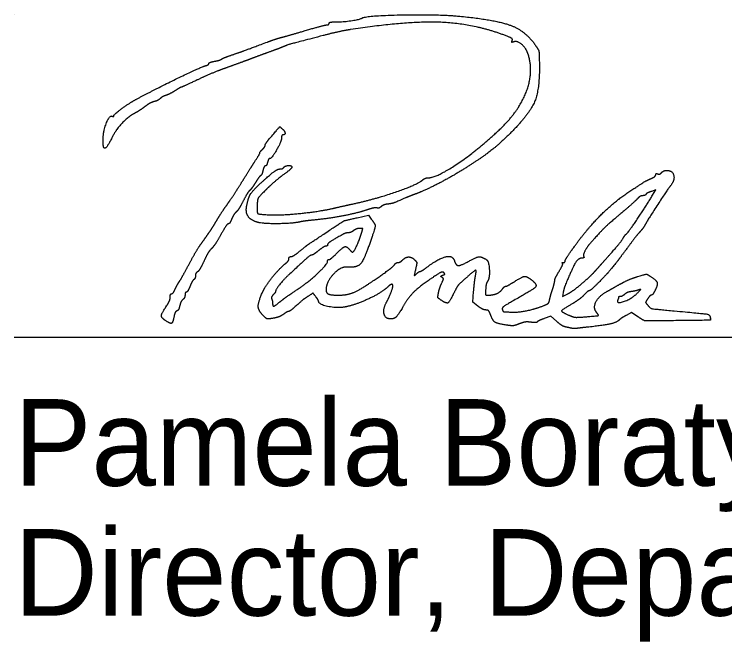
# Model space of a CAD drawing. Extents: x -8.2 to 38.5, y -0.1 to 21.9.
# Drawn here: x 24.597 to 25.745, y 6.87 to 7.884 of the extents above; entities that cross this region are included whole.
import ezdxf

# ---------------------------------------------------------------- set-up
doc = ezdxf.new("R2010")
doc.units = 0
doc.layers.add('GM_X_Adjacent_County', color=7, linetype='Continuous')
doc.layers.add('GM_X_Township', color=7, linetype='Continuous')

msp = doc.modelspace()

# ---------------------------------------------------------------- linework, layer by layer
at = {"layer": 'GM_X_Adjacent_County'}
for points in [[(25.6284, 7.5917), (25.6338, 7.6006), (25.6265, 7.598)], [(25.1511, 7.5555), (25.1691, 7.5595), (25.1738, 7.5534)], [(25.346, 7.4127), (25.3377, 7.419), (25.3392, 7.4361)], [(25.484, 7.4347), (25.483, 7.4282), (25.4917, 7.4326)], [(25.6049, 7.3953), (25.5942, 7.4022), (25.5858, 7.3976)], [(25.473, 7.3883), (25.4638, 7.3966), (25.4533, 7.3925)]]:
    msp.add_lwpolyline(points, dxfattribs=at)
for points in [[(25.1585, 7.8781), (25.1653, 7.8823), (25.2823, 7.8845), (25.3167, 7.8812)], [(25.3167, 7.8812), (25.376, 7.8753), (25.4235, 7.857), (25.4393, 7.834)], [(25.1018, 7.8671), (25.1038, 7.8671), (25.1055, 7.8683), (25.1055, 7.8696)], [(25.1055, 7.8696), (25.1055, 7.871), (25.1096, 7.872), (25.1145, 7.8719)], [(25.1145, 7.8719), (25.1241, 7.8716), (25.1551, 7.8759), (25.1585, 7.8781)], [(25.3892, 7.8504), (25.3386, 7.8694), (25.2307, 7.8734), (25.1403, 7.8596)], [(25.0299, 7.8473), (25.0352, 7.8487), (25.0527, 7.8537), (25.0688, 7.8585)], [(25.0688, 7.8585), (25.0849, 7.8632), (25.0997, 7.8671), (25.1018, 7.8671)], [(25.1403, 7.8596), (25.1311, 7.8582), (25.1111, 7.8539), (25.0959, 7.8499)], [(25.0059, 7.8395), (25.0138, 7.8424), (25.0246, 7.846), (25.0299, 7.8473)], [(25.0959, 7.8499), (25.0449, 7.8367), (25.0406, 7.8355), (25.0299, 7.8311)], [(25.4015, 7.8418), (25.4025, 7.8443), (25.399, 7.8467), (25.3892, 7.8504)], [(24.9495, 7.8189), (24.9642, 7.824), (24.9707, 7.8264), (25.0059, 7.8395)], [(25.4039, 7.8397), (25.4013, 7.8387), (25.4006, 7.8394), (25.4015, 7.8418)], [(25.4273, 7.8198), (25.4241, 7.8296), (25.4096, 7.8419), (25.4039, 7.8397)], [(25.4393, 7.834), (25.4443, 7.8267), (25.4452, 7.8224), (25.4455, 7.8045)], [(25.0071, 7.8227), (24.9972, 7.8191), (24.9821, 7.8135), (24.9735, 7.8102)], [(25.0299, 7.8311), (25.0273, 7.8301), (25.017, 7.8263), (25.0071, 7.8227)], [(24.9201, 7.8083), (24.9251, 7.8092), (24.9302, 7.8108), (24.9315, 7.8117)], [(24.9315, 7.8117), (24.9328, 7.8127), (24.9409, 7.816), (24.9495, 7.8189)], [(25.3818, 7.6986), (25.4128, 7.728), (25.4366, 7.7916), (25.4273, 7.8198)], [(24.7935, 7.7467), (24.8237, 7.763), (24.8973, 7.7986), (24.9057, 7.8011)], [(24.9057, 7.8011), (24.9087, 7.8019), (24.9111, 7.8035), (24.9111, 7.8046)], [(24.9111, 7.8046), (24.9111, 7.8057), (24.9152, 7.8074), (24.9201, 7.8083)], [(24.9735, 7.8102), (24.9649, 7.807), (24.9487, 7.8011), (24.9375, 7.7971)], [(25.4455, 7.8045), (25.4462, 7.7638), (25.4301, 7.7241), (25.4007, 7.6942)], [(24.9375, 7.7971), (24.9263, 7.7931), (24.9059, 7.7846), (24.8923, 7.7781)], [(24.8923, 7.7781), (24.8786, 7.7716), (24.867, 7.7663), (24.8664, 7.7663)], [(24.8664, 7.7663), (24.8659, 7.7663), (24.8614, 7.7638), (24.8565, 7.7607)], [(24.8416, 7.7532), (24.8384, 7.7521), (24.8343, 7.7498), (24.8325, 7.748)], [(24.8565, 7.7607), (24.8515, 7.7576), (24.8449, 7.7542), (24.8416, 7.7532)], [(24.7575, 7.7201), (24.7575, 7.7223), (24.7829, 7.741), (24.7935, 7.7467)], [(24.8227, 7.7432), (24.8192, 7.7423), (24.8125, 7.7387), (24.8079, 7.7351)], [(24.8325, 7.748), (24.8306, 7.7462), (24.8263, 7.744), (24.8227, 7.7432)], [(24.8079, 7.7351), (24.8033, 7.7315), (24.7961, 7.7269), (24.792, 7.7248)], [(24.7403, 7.6822), (24.7404, 7.6954), (24.7511, 7.722), (24.7552, 7.7195)], [(24.7552, 7.7195), (24.7565, 7.7187), (24.7575, 7.719), (24.7575, 7.7201)], [(24.792, 7.7248), (24.7816, 7.7194), (24.7617, 7.6986), (24.7555, 7.6865)], [(25.0077, 7.6812), (25.0262, 7.7033), (25.0256, 7.7027), (25.0296, 7.6994)], [(25.0296, 7.6994), (25.0339, 7.6958), (25.0349, 7.6895), (25.0311, 7.6895)], [(25.2651, 7.6199), (25.2792, 7.6199), (25.3473, 7.6658), (25.3818, 7.6986)], [(24.7555, 7.6865), (24.7489, 7.6736), (24.7436, 7.6667), (24.7417, 7.6685)], [(25.0287, 7.6844), (25.0287, 7.6789), (25.0128, 7.6511), (25.0096, 7.6511)], [(25.0311, 7.6895), (25.0298, 7.6895), (25.0287, 7.6872), (25.0287, 7.6844)], [(25.4007, 7.6942), (25.3821, 7.6753), (25.3497, 7.6504), (25.3192, 7.6315)], [(24.7417, 7.6685), (24.7409, 7.6693), (24.7403, 7.6755), (24.7403, 7.6822)], [(24.9975, 7.6655), (25.0001, 7.6682), (25.0023, 7.6713), (25.0023, 7.6725)], [(25.0023, 7.6725), (25.0023, 7.6737), (25.0047, 7.6776), (25.0077, 7.6812)], [(24.9938, 7.6607), (24.9932, 7.6607), (24.9949, 7.6629), (24.9975, 7.6655)], [(24.9848, 7.6451), (24.9903, 7.6537), (24.9943, 7.6607), (24.9938, 7.6607)], [(25.0096, 7.6511), (25.0085, 7.6511), (25.007, 7.6484), (25.0061, 7.6451)], [(24.9627, 7.6101), (24.9693, 7.6207), (24.9792, 7.6365), (24.9848, 7.6451)], [(25.0025, 7.6391), (25.0013, 7.6391), (24.9996, 7.6359), (24.9987, 7.632)], [(25.0061, 7.6451), (25.0053, 7.6418), (25.0036, 7.6391), (25.0025, 7.6391)], [(25.0323, 7.6367), (25.0341, 7.6396), (25.0455, 7.64), (25.0455, 7.6371)], [(24.9939, 7.6102), (25.0096, 7.6248), (25.0224, 7.6343), (25.0263, 7.6343)], [(24.9987, 7.632), (24.9978, 7.628), (24.9961, 7.6241), (24.9948, 7.6234)], [(25.0263, 7.6343), (25.0288, 7.6343), (25.0315, 7.6354), (25.0323, 7.6367)], [(25.0455, 7.6371), (25.0455, 7.636), (25.0388, 7.6301), (25.0305, 7.624)], [(25.3192, 7.6315), (25.3001, 7.6197), (25.2588, 7.5987), (25.2447, 7.5936)], [(25.6335, 7.6249), (25.6335, 7.6264), (25.635, 7.6271), (25.6369, 7.6263)], [(25.6369, 7.6263), (25.6388, 7.6256), (25.6416, 7.6266), (25.6432, 7.6285)], [(25.6432, 7.6285), (25.6448, 7.6304), (25.6485, 7.6319), (25.6514, 7.6319)], [(25.6514, 7.6319), (25.6609, 7.6319), (25.6646, 7.6159), (25.6572, 7.6069)], [(24.9948, 7.6234), (24.9936, 7.6226), (24.9897, 7.6174), (24.9864, 7.6119)], [(25.0305, 7.624), (25.0223, 7.6179), (25.0098, 7.607), (25.0027, 7.5998)], [(25.1451, 7.578), (25.182, 7.5862), (25.2483, 7.6091), (25.2569, 7.6166)], [(25.2569, 7.6166), (25.259, 7.6184), (25.2627, 7.6199), (25.2651, 7.6199)], [(25.5967, 7.6015), (25.6157, 7.6138), (25.6175, 7.6149), (25.6257, 7.6186)], [(25.6257, 7.6186), (25.63, 7.6205), (25.6335, 7.6233), (25.6335, 7.6249)], [(24.941, 7.5771), (24.9463, 7.5846), (24.9561, 7.5994), (24.9627, 7.6101)], [(24.9726, 7.5755), (24.9753, 7.5886), (24.9815, 7.5986), (24.9939, 7.6102)], [(24.9864, 7.6119), (24.983, 7.6064), (24.9788, 7.6008), (24.9772, 7.5995)], [(25.6572, 7.6069), (25.6531, 7.6019), (25.6202, 7.5514), (25.6171, 7.5453)], [(24.9772, 7.5995), (24.9755, 7.5982), (24.9709, 7.5905), (24.9668, 7.5826)], [(25.0027, 7.5998), (24.992, 7.5889), (24.9898, 7.5852), (24.9893, 7.577)], [(25.2447, 7.5936), (25.2401, 7.5919), (25.2331, 7.5891), (25.2291, 7.5874)], [(25.5021, 7.509), (25.5244, 7.5398), (25.5694, 7.5839), (25.5967, 7.6015)], [(25.6178, 7.5933), (25.617, 7.5921), (25.6146, 7.5911), (25.6124, 7.5911)], [(25.6265, 7.598), (25.6224, 7.5966), (25.6185, 7.5945), (25.6178, 7.5933)], [(24.9668, 7.5826), (24.9628, 7.5746), (24.9577, 7.5666), (24.9556, 7.5648)], [(25.2291, 7.5874), (25.212, 7.58), (25.2071, 7.5783), (25.2005, 7.5775)], [(25.6036, 7.5857), (25.6009, 7.5828), (25.5884, 7.5717), (25.5759, 7.5612)], [(25.5856, 7.5287), (25.5884, 7.5307), (25.6167, 7.5722), (25.6284, 7.5917)], [(25.6124, 7.5911), (25.6103, 7.5911), (25.6063, 7.5887), (25.6036, 7.5857)], [(24.9242, 7.5515), (24.9281, 7.5581), (24.9356, 7.5697), (24.941, 7.5771)], [(24.9879, 7.5487), (24.9775, 7.5526), (24.9704, 7.565), (24.9726, 7.5755)], [(24.9893, 7.577), (24.9885, 7.5635), (24.9925, 7.5607), (25.0131, 7.5601)], [(25.0131, 7.5601), (25.0324, 7.5596), (25.0902, 7.5657), (25.1115, 7.5705)], [(25.1115, 7.5705), (25.1194, 7.5723), (25.1345, 7.5757), (25.1451, 7.578)], [(25.1829, 7.5713), (25.1812, 7.5719), (25.1731, 7.5702), (25.1649, 7.5675)], [(25.1897, 7.5734), (25.1876, 7.5716), (25.1846, 7.5707), (25.1829, 7.5713)], [(25.2005, 7.5775), (25.1966, 7.5771), (25.1918, 7.5752), (25.1897, 7.5734)], [(24.9556, 7.5648), (24.9534, 7.563), (24.9501, 7.5579), (24.9483, 7.5535)], [(25.1649, 7.5675), (25.1484, 7.5622), (25.1033, 7.5538), (25.0796, 7.5515)], [(25.5759, 7.5612), (25.5563, 7.5446), (25.5446, 7.5332), (25.5279, 7.5144)], [(24.9112, 7.5309), (24.9145, 7.5356), (24.9204, 7.5449), (24.9242, 7.5515)], [(24.9483, 7.5535), (24.9465, 7.5491), (24.9439, 7.5455), (24.9426, 7.5455)], [(25.0592, 7.5488), (25.0454, 7.5458), (24.9959, 7.5457), (24.9879, 7.5487)], [(25.0796, 7.5515), (25.0712, 7.5507), (25.062, 7.5495), (25.0592, 7.5488)], [(25.0971, 7.5291), (25.1288, 7.5501), (25.1302, 7.5508), (25.1511, 7.5555)], [(25.1738, 7.5534), (25.1804, 7.5446), (25.1802, 7.5397), (25.1725, 7.5172)], [(24.9426, 7.5455), (24.9413, 7.5455), (24.9359, 7.5376), (24.9306, 7.528)], [(25.1453, 7.5347), (25.1427, 7.5327), (25.1388, 7.5311), (25.1365, 7.5311)], [(25.1551, 7.5383), (25.1523, 7.5382), (25.1478, 7.5366), (25.1453, 7.5347)], [(25.1584, 7.5317), (25.1601, 7.5375), (25.1597, 7.5383), (25.1551, 7.5383)], [(25.6171, 7.5453), (25.6153, 7.5418), (25.6114, 7.5364), (25.6084, 7.5331)], [(24.8976, 7.5117), (24.9018, 7.5175), (24.9078, 7.5261), (24.9112, 7.5309)], [(24.9306, 7.528), (24.9252, 7.5183), (24.9185, 7.5083), (24.9157, 7.5058)], [(25.0579, 7.5012), (25.0716, 7.5122), (25.0696, 7.5108), (25.0971, 7.5291)], [(25.1268, 7.528), (25.1124, 7.5201), (25.1031, 7.5137), (25.1031, 7.5117)], [(25.1365, 7.5311), (25.1343, 7.5311), (25.1299, 7.5297), (25.1268, 7.528)], [(25.1438, 7.4999), (25.1456, 7.4999), (25.1553, 7.5211), (25.1584, 7.5317)], [(25.5504, 7.4858), (25.5658, 7.5029), (25.5793, 7.5193), (25.5817, 7.5236)], [(25.5817, 7.5236), (25.5829, 7.5258), (25.5847, 7.5281), (25.5856, 7.5287)], [(25.6084, 7.5331), (25.6054, 7.5299), (25.5965, 7.5186), (25.5886, 7.5079)], [(24.8788, 7.4795), (24.885, 7.4914), (24.8935, 7.5059), (24.8976, 7.5117)], [(25.1031, 7.5117), (25.1031, 7.5105), (25.1019, 7.5095), (25.1005, 7.5095)], [(25.1725, 7.5172), (25.1623, 7.4873), (25.1503, 7.4742), (25.1343, 7.4756)], [(25.5279, 7.5144), (25.5221, 7.5077), (25.5158, 7.4949), (25.5172, 7.4925)], [(24.9157, 7.5058), (24.9129, 7.5032), (24.9073, 7.4941), (24.9034, 7.4855)], [(25.0441, 7.4927), (25.0459, 7.4927), (25.0521, 7.4965), (25.0579, 7.5012)], [(25.0887, 7.5023), (25.0837, 7.4984), (25.0787, 7.4951), (25.0776, 7.4951)], [(25.1005, 7.5095), (25.099, 7.5095), (25.0937, 7.5063), (25.0887, 7.5023)], [(25.1175, 7.4975), (25.1276, 7.5077), (25.1342, 7.5095), (25.1391, 7.5035)], [(25.1391, 7.5035), (25.1408, 7.5016), (25.1428, 7.4999), (25.1438, 7.4999)], [(25.4871, 7.4857), (25.4871, 7.4871), (25.4939, 7.4976), (25.5021, 7.509)], [(25.5886, 7.5079), (25.5807, 7.4973), (25.5731, 7.4871), (25.5716, 7.4852)], [(25.0353, 7.4815), (25.0383, 7.4839), (25.0407, 7.4874), (25.0407, 7.4893)], [(25.0407, 7.4893), (25.0407, 7.4912), (25.0422, 7.4927), (25.0441, 7.4927)], [(25.0776, 7.4951), (25.0757, 7.4951), (25.0672, 7.4879), (25.0419, 7.4646)], [(25.1055, 7.4879), (25.1068, 7.4879), (25.1122, 7.4923), (25.1175, 7.4975)], [(25.2243, 7.487), (25.2292, 7.492), (25.2392, 7.4921), (25.2441, 7.4871)], [(25.2623, 7.4745), (25.2825, 7.4896), (25.3052, 7.4952), (25.3082, 7.4858)], [(25.332, 7.4854), (25.344, 7.492), (25.3512, 7.4928), (25.3594, 7.4882)], [(25.515, 7.4903), (25.5086, 7.4903), (25.4991, 7.4752), (25.4871, 7.4459)], [(25.5172, 7.4925), (25.518, 7.4913), (25.517, 7.4903), (25.515, 7.4903)], [(24.8633, 7.4519), (24.8655, 7.4552), (24.8725, 7.4677), (24.8788, 7.4795)], [(24.9034, 7.4855), (24.8995, 7.477), (24.8947, 7.4691), (24.8929, 7.468)], [(24.9972, 7.4333), (25.0017, 7.4437), (25.0249, 7.4732), (25.0353, 7.4815)], [(25.057, 7.4414), (25.0726, 7.4518), (25.1031, 7.4805), (25.1031, 7.4848)], [(25.1031, 7.4848), (25.1031, 7.4865), (25.1042, 7.4879), (25.1055, 7.4879)], [(25.1691, 7.4483), (25.1877, 7.4606), (25.2101, 7.4773), (25.2118, 7.4801)], [(25.2118, 7.4801), (25.2129, 7.4818), (25.2152, 7.4831), (25.2171, 7.4831)], [(25.2171, 7.4831), (25.2189, 7.4831), (25.2221, 7.4849), (25.2243, 7.487)], [(25.2441, 7.4871), (25.2473, 7.484), (25.2475, 7.4815), (25.2454, 7.4723)], [(25.3082, 7.4858), (25.3106, 7.4782), (25.3187, 7.4781), (25.332, 7.4854)], [(25.3594, 7.4882), (25.3638, 7.4857), (25.3655, 7.4577), (25.3616, 7.4525)], [(25.4773, 7.4688), (25.4812, 7.4751), (25.4837, 7.4809), (25.4829, 7.4817)], [(25.4829, 7.4817), (25.4822, 7.4825), (25.4828, 7.4831), (25.4843, 7.4831)], [(25.4843, 7.4831), (25.4858, 7.4831), (25.4871, 7.4843), (25.4871, 7.4857)], [(25.5348, 7.4683), (25.5379, 7.4718), (25.545, 7.4797), (25.5504, 7.4858)], [(25.5716, 7.4852), (25.5583, 7.4688), (25.5538, 7.4637), (25.5419, 7.4515)], [(24.8929, 7.468), (24.891, 7.467), (24.8895, 7.4641), (24.8895, 7.4616)], [(25.1343, 7.4756), (25.1239, 7.4765), (25.1007, 7.4511), (25.1007, 7.4388)], [(25.2454, 7.4723), (25.2431, 7.4621), (25.2432, 7.4616), (25.247, 7.465)], [(25.247, 7.465), (25.2493, 7.4671), (25.2519, 7.4687), (25.2529, 7.4687)], [(25.2529, 7.4687), (25.2538, 7.4687), (25.2581, 7.4713), (25.2623, 7.4745)], [(25.291, 7.4667), (25.2891, 7.4685), (25.2832, 7.4657), (25.2708, 7.4572)], [(25.2893, 7.4625), (25.2923, 7.4636), (25.2928, 7.4648), (25.291, 7.4667)], [(25.3421, 7.4609), (25.344, 7.4704), (25.3414, 7.4708), (25.3321, 7.4626)], [(25.4703, 7.4541), (25.4703, 7.4559), (25.4735, 7.4625), (25.4773, 7.4688)], [(25.5147, 7.4495), (25.5226, 7.4563), (25.5317, 7.4648), (25.5348, 7.4683)], [(24.887, 7.4555), (24.8856, 7.4546), (24.8828, 7.4497), (24.8807, 7.4445)], [(24.8895, 7.4616), (24.8895, 7.4591), (24.8884, 7.4563), (24.887, 7.4555)], [(25.0419, 7.4646), (25.0328, 7.4562), (25.0191, 7.4392), (25.0191, 7.4362)], [(25.2708, 7.4572), (25.251, 7.4438), (25.2338, 7.4267), (25.2255, 7.4123)], [(25.2881, 7.459), (25.2859, 7.4604), (25.2862, 7.4613), (25.2893, 7.4625)], [(25.2874, 7.4492), (25.2903, 7.4554), (25.2904, 7.4576), (25.2881, 7.459)], [(25.3321, 7.4626), (25.3161, 7.4486), (25.3124, 7.4441), (25.3069, 7.4328)], [(25.3392, 7.4361), (25.34, 7.4455), (25.3413, 7.4566), (25.3421, 7.4609)], [(25.4329, 7.4549), (25.4426, 7.4473), (25.4358, 7.4394), (25.4042, 7.4217)], [(25.4047, 7.4519), (25.4177, 7.4602), (25.4252, 7.461), (25.4329, 7.4549)], [(25.5747, 7.4475), (25.5826, 7.452), (25.5958, 7.4577), (25.604, 7.4602)], [(25.604, 7.4602), (25.6181, 7.4644), (25.6192, 7.4644), (25.6251, 7.4606)], [(25.6251, 7.4606), (25.6347, 7.4543), (25.6371, 7.4469), (25.6325, 7.4379)], [(24.8564, 7.4393), (24.858, 7.443), (24.8611, 7.4486), (24.8633, 7.4519)], [(24.8807, 7.4445), (24.8787, 7.4394), (24.876, 7.4351), (24.8748, 7.4351)], [(25.1207, 7.4303), (25.1337, 7.4303), (25.1528, 7.4374), (25.1691, 7.4483)], [(25.2011, 7.4441), (25.1915, 7.435), (25.1528, 7.4162), (25.1343, 7.4117)], [(25.1981, 7.4183), (25.2023, 7.426), (25.2087, 7.4423), (25.2087, 7.445)], [(25.2087, 7.445), (25.2087, 7.4481), (25.2047, 7.4476), (25.2011, 7.4441)], [(25.2823, 7.4335), (25.2831, 7.4377), (25.2854, 7.4447), (25.2874, 7.4492)], [(25.3616, 7.4525), (25.3603, 7.4509), (25.359, 7.4452), (25.3587, 7.4399)], [(25.3856, 7.4399), (25.3874, 7.4425), (25.39, 7.4447), (25.3912, 7.4447)], [(25.3912, 7.4447), (25.3924, 7.4447), (25.3985, 7.448), (25.4047, 7.4519)], [(25.4668, 7.4399), (25.4687, 7.4459), (25.4703, 7.4522), (25.4703, 7.4541)], [(25.4871, 7.4459), (25.486, 7.4433), (25.4846, 7.4382), (25.484, 7.4347)], [(25.4917, 7.4326), (25.4964, 7.4351), (25.5068, 7.4427), (25.5147, 7.4495)], [(25.5419, 7.4515), (25.5344, 7.4438), (25.5274, 7.4375), (25.5263, 7.4375)], [(25.5551, 7.4365), (25.558, 7.438), (25.5668, 7.443), (25.5747, 7.4475)], [(24.8487, 7.4271), (24.8487, 7.4302), (24.8498, 7.4327), (24.8512, 7.4327)], [(24.8512, 7.4327), (24.8525, 7.4327), (24.8549, 7.4357), (24.8564, 7.4393)], [(24.8748, 7.4351), (24.8737, 7.4351), (24.8727, 7.4331), (24.8727, 7.4306)], [(24.9989, 7.3975), (24.9913, 7.4052), (24.9907, 7.418), (24.9972, 7.4333)], [(25.0191, 7.4362), (25.0191, 7.4354), (25.0174, 7.4331), (25.0154, 7.4311)], [(25.0255, 7.419), (25.033, 7.4251), (25.0383, 7.4288), (25.057, 7.4414)], [(25.0841, 7.4278), (25.0796, 7.4336), (25.0796, 7.4336), (25.0728, 7.4292)], [(25.1007, 7.4388), (25.1007, 7.4337), (25.1085, 7.4303), (25.1207, 7.4303)], [(25.2869, 7.422), (25.2819, 7.4253), (25.2812, 7.4273), (25.2823, 7.4335)], [(25.3069, 7.4328), (25.3002, 7.4191), (25.2954, 7.4165), (25.2869, 7.422)], [(25.3587, 7.4399), (25.3581, 7.4323), (25.3588, 7.4303), (25.362, 7.4303)], [(25.362, 7.4303), (25.3703, 7.4303), (25.3823, 7.4352), (25.3856, 7.4399)], [(25.462, 7.4229), (25.4627, 7.4263), (25.4649, 7.434), (25.4668, 7.4399)], [(25.5263, 7.4375), (25.5252, 7.4375), (25.5213, 7.4344), (25.5177, 7.4306)], [(25.5381, 7.4021), (25.532, 7.4095), (25.5418, 7.4292), (25.5551, 7.4365)], [(25.5721, 7.4222), (25.5696, 7.4157), (25.595, 7.4246), (25.6035, 7.4333)], [(25.5831, 7.4315), (25.5809, 7.4296), (25.5779, 7.4279), (25.5763, 7.4279)], [(25.5941, 7.4361), (25.5902, 7.4355), (25.5853, 7.4335), (25.5831, 7.4315)], [(25.6059, 7.4388), (25.6033, 7.4378), (25.598, 7.4366), (25.5941, 7.4361)], [(25.6035, 7.4333), (25.609, 7.4388), (25.6096, 7.4402), (25.6059, 7.4388)], [(25.6325, 7.4379), (25.6303, 7.4337), (25.6277, 7.4303), (25.6265, 7.4303)], [(24.8429, 7.4128), (24.8461, 7.4176), (24.8487, 7.424), (24.8487, 7.4271)], [(24.8693, 7.4233), (24.8674, 7.4217), (24.8651, 7.4172), (24.8642, 7.4132)], [(24.8727, 7.4306), (24.8727, 7.4282), (24.8712, 7.4248), (24.8693, 7.4233)], [(25.0154, 7.4311), (25.0133, 7.429), (25.0122, 7.4257), (25.013, 7.4238)], [(25.013, 7.4238), (25.0137, 7.4219), (25.0143, 7.4188), (25.0143, 7.4169)], [(25.0728, 7.4292), (25.0646, 7.4238), (25.062, 7.4218), (25.0508, 7.4117)], [(25.0887, 7.4204), (25.0886, 7.4212), (25.0866, 7.4246), (25.0841, 7.4278)], [(25.1343, 7.4117), (25.1214, 7.4086), (25.0888, 7.4148), (25.0887, 7.4204)], [(25.4042, 7.4217), (25.3909, 7.4142), (25.3847, 7.4094), (25.3856, 7.4072)], [(25.4493, 7.4122), (25.4581, 7.4156), (25.4611, 7.4181), (25.462, 7.4229)], [(25.5177, 7.4306), (25.5141, 7.4268), (25.506, 7.4206), (25.4997, 7.417)], [(25.5735, 7.4269), (25.5735, 7.4264), (25.5729, 7.4242), (25.5721, 7.4222)], [(25.5763, 7.4279), (25.5748, 7.4279), (25.5735, 7.4275), (25.5735, 7.4269)], [(25.6207, 7.4245), (25.6171, 7.4192), (25.6172, 7.4183), (25.621, 7.4136)], [(25.6265, 7.4303), (25.6254, 7.4303), (25.6227, 7.4277), (25.6207, 7.4245)], [(24.8412, 7.3891), (24.8342, 7.394), (24.8347, 7.4007), (24.8429, 7.4128)], [(24.8642, 7.4132), (24.8634, 7.4092), (24.8612, 7.4055), (24.8595, 7.4048)], [(25.0143, 7.4169), (25.0143, 7.4121), (25.0177, 7.4127), (25.0255, 7.419)], [(25.0508, 7.4117), (25.046, 7.4074), (25.0412, 7.4039), (25.0401, 7.4039)], [(25.2049, 7.3919), (25.1965, 7.3919), (25.1924, 7.4077), (25.1981, 7.4183)], [(25.2255, 7.4123), (25.2173, 7.3982), (25.211, 7.3919), (25.2049, 7.3919)], [(25.3591, 7.4063), (25.3565, 7.4063), (25.3506, 7.4092), (25.346, 7.4127)], [(25.3995, 7.4029), (25.41, 7.4023), (25.4362, 7.4072), (25.4493, 7.4122)], [(25.4997, 7.417), (25.4818, 7.4066), (25.4808, 7.4033), (25.4937, 7.3977)], [(25.621, 7.4136), (25.6247, 7.4091), (25.6296, 7.408), (25.6635, 7.4049)], [(24.8595, 7.4048), (24.8578, 7.4041), (24.8557, 7.4), (24.8549, 7.3956)], [(25.0151, 7.3929), (25.0064, 7.3916), (25.0042, 7.3922), (24.9989, 7.3975)], [(25.0316, 7.3992), (25.028, 7.3966), (25.0206, 7.3938), (25.0151, 7.3929)], [(25.0401, 7.4039), (25.039, 7.4039), (25.0352, 7.4018), (25.0316, 7.3992)], [(25.3666, 7.3985), (25.3647, 7.4037), (25.3622, 7.4063), (25.3591, 7.4063)], [(25.3919, 7.382), (25.3769, 7.3844), (25.3701, 7.3889), (25.3666, 7.3985)], [(25.3856, 7.4072), (25.3869, 7.4038), (25.3876, 7.4036), (25.3995, 7.4029)], [(25.4937, 7.3977), (25.5005, 7.3948), (25.507, 7.3942), (25.5205, 7.3953)], [(25.5205, 7.3953), (25.54, 7.3969), (25.5418, 7.3976), (25.5381, 7.4021)], [(25.5858, 7.3976), (25.5812, 7.3952), (25.576, 7.3916), (25.5741, 7.3898)], [(25.6635, 7.4049), (25.7126, 7.4004), (25.7209, 7.3988), (25.7218, 7.394)], [(24.8549, 7.3956), (24.853, 7.3858), (24.8489, 7.3839), (24.8412, 7.3891)], [(25.4319, 7.3865), (25.4261, 7.3873), (25.4188, 7.3863), (25.413, 7.3839)], [(25.442, 7.3868), (25.4416, 7.386), (25.4371, 7.3858), (25.4319, 7.3865)], [(25.4533, 7.3925), (25.4475, 7.3903), (25.4424, 7.3877), (25.442, 7.3868)], [(25.4876, 7.3789), (25.4846, 7.3795), (25.4781, 7.3838), (25.473, 7.3883)], [(25.5741, 7.3898), (25.5704, 7.3861), (25.5489, 7.3812), (25.5255, 7.3788)], [(25.6515, 7.3889), (25.6158, 7.3885), (25.6154, 7.3886), (25.6049, 7.3953)], [(25.7218, 7.394), (25.7226, 7.3898), (25.7207, 7.3897), (25.6515, 7.3889)], [(25.413, 7.3839), (25.4061, 7.3812), (25.4005, 7.3806), (25.3919, 7.382)], [(25.4979, 7.3767), (25.4953, 7.3773), (25.4907, 7.3782), (25.4876, 7.3789)], [(25.5063, 7.3765), (25.5043, 7.3761), (25.5005, 7.3762), (25.4979, 7.3767)], [(25.5255, 7.3788), (25.5169, 7.3779), (25.5083, 7.3769), (25.5063, 7.3765)]]:
    msp.add_open_spline(points, degree=2, dxfattribs=at)
at = {"layer": 'GM_X_Township'}
for p, q in [((24.5966, 7.8844), (24.5966, 7.8844)), ((24.5966, 7.3622), (28.0966, 7.3622))]:
    msp.add_line(p, q, dxfattribs=at)

# ---------------------------------------------------------------- texts
at = {"layer": 'GM_X_Adjacent_County'}
for s, p in [('Pamela Boratyn', (24.5966, 7.1222)), ('Director, Department of Transportation', (24.5966, 6.9122))]:
    msp.add_text(s, height=0.14, dxfattribs=at).set_placement(p)

doc.saveas('drawing.dxf')
